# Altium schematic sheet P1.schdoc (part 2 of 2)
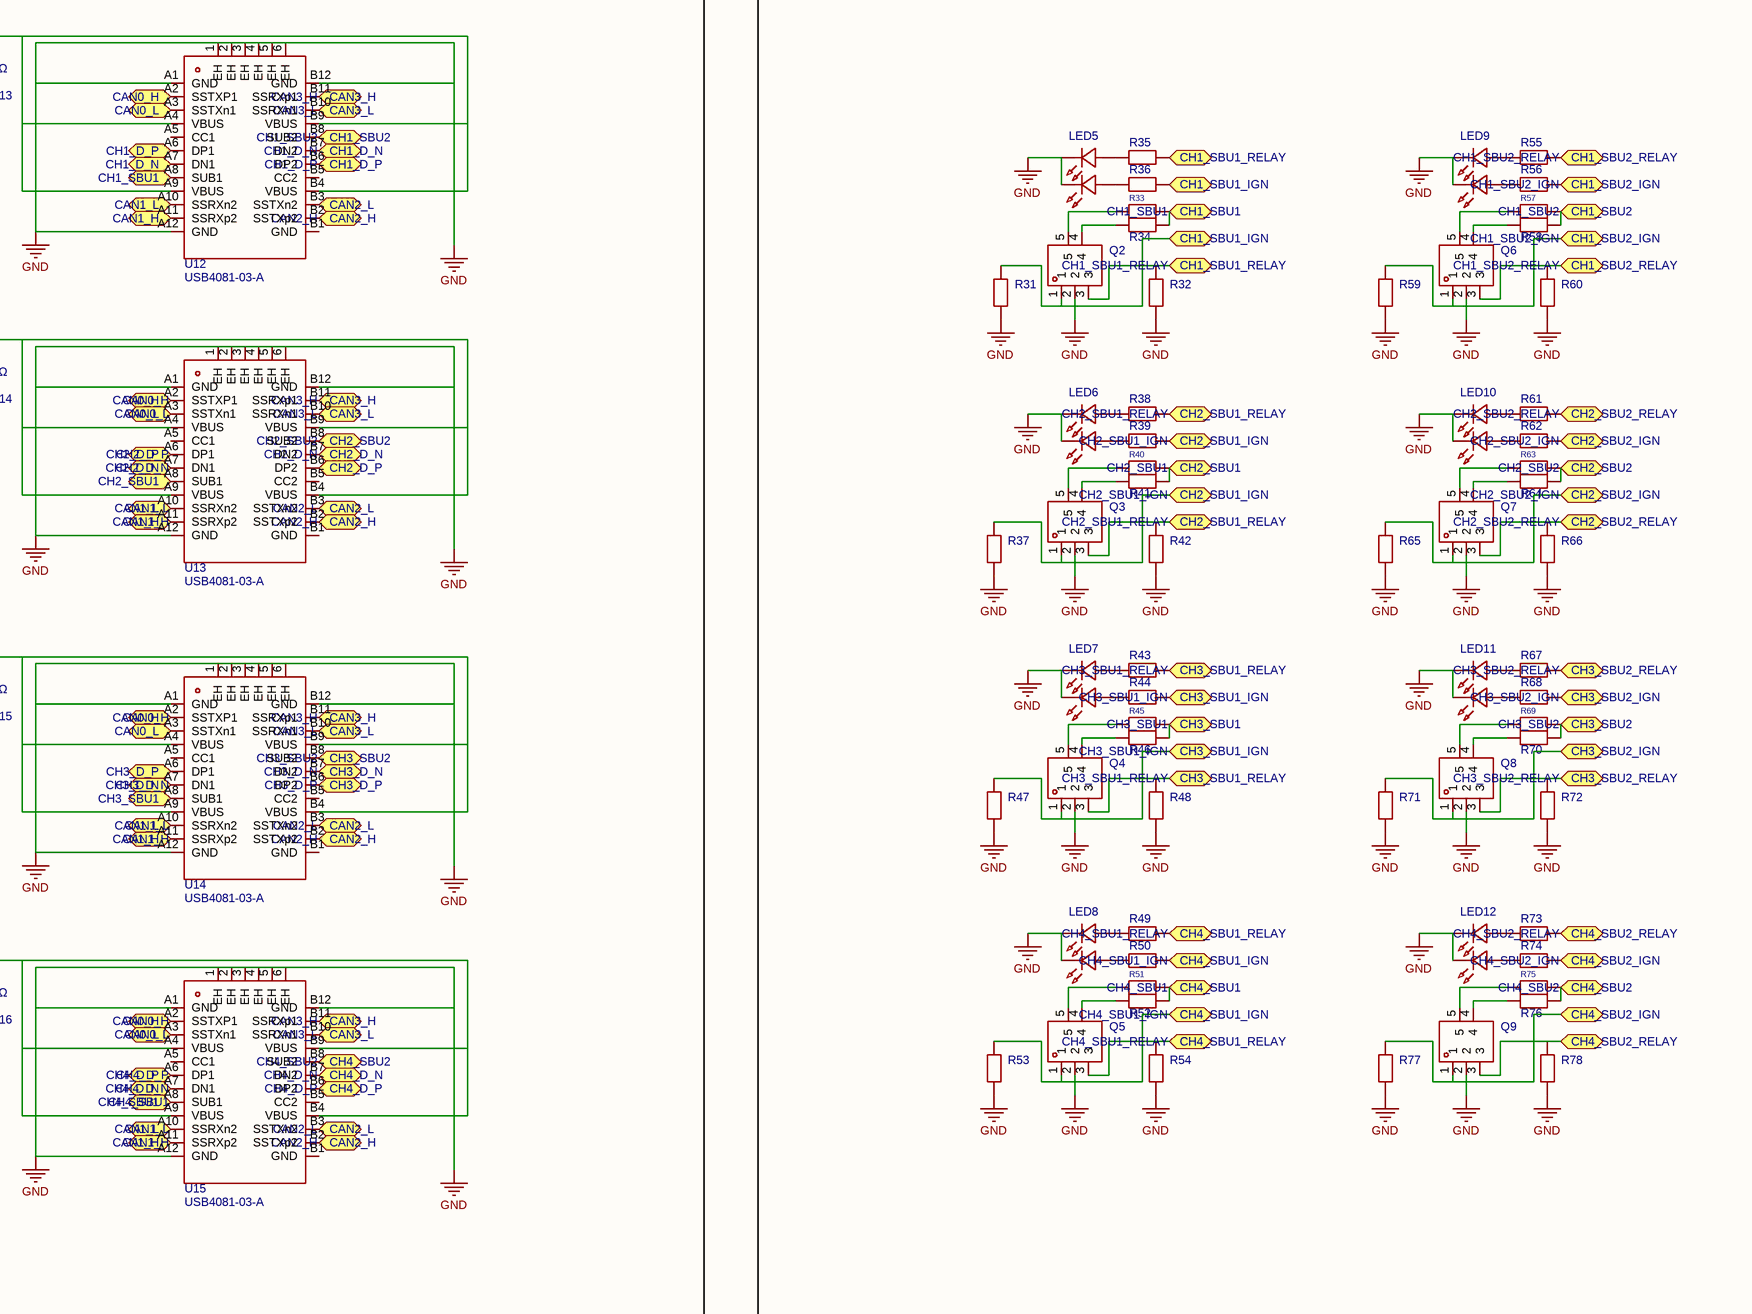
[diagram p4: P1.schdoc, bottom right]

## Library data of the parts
C1 C2 C7 C8 C13 C30 C31 C37 = CL05A106MQ5NUNC: Capacitance:10uF Tolerance:±20% Tolerance:±20% Voltage Rating:6.3V Temperature Coefficient:X5R; Manufacturer: SAMSUNG(三星); AddInBom: yes; ModelId: b7d13df3e9464d7a99d0651d1a5b4d570819f05c4eef4c71ace90d822a990e87; ModelName: C0402_L1.0-W0.5-H0.5; ModelTransform: 39.37,19.685,0,0,0,0,0,0,0; Tolerance: ±20%; Voltage Rating: 6.3V; Temperature Coefficient: X5R
C3 C5 C6 C9 C11 C12 C14 C32-C36 = FCC0201X104K100ZT: Capacitance:100nF Tolerance:±10% Tolerance:±10% Voltage Rating:10V Temperature Coefficient:X5R Operating Temperature:-55℃~+85℃ Operating Temperature:-55℃~+85℃; Manufacturer: FOJAN(富捷); AddInBom: yes; ModelId: c3e75c3d90204c70b153866ab54c789f0819f05c4eef4c71ace90d822a990e87; ModelName: C0201_L0.6-W0.3-H0.3; ModelTransform: 23.622,11.811,0,0,0,0,0,0,0; Tolerance: ±10%; Voltage Rating: 10V; Temperature Coefficient: X5R
C4 C10 C15-C25 C40 C41 C46 C47 C50 C51 = FCC0201X104K100ZT: Capacitance:100nF Tolerance:±10% Tolerance:±10% Voltage Rating:10V Temperature Coefficient:X5R Operating Temperature:-55℃~+85℃ Operating Temperature:-55℃~+85℃; Manufacturer: FOJAN(富捷); 3D Model: c3e75c3d90204c70b153866ab54c789f0819f05c4eef4c71ace90d822a990e87; 3D Model Transform: 23.622,11.811,0,0,0,0,0,0,0; Tolerance: ±10%; Voltage Rating: 10V; Temperature Coefficient: X5R; AddInBom: yes; ModelName: C0201_L0.6-W0.3-H0.3
C26-C29 = GRM035R60G106ME01D: Capacitance:10uF Tolerance:±20% Tolerance:±20% Voltage Rating:4V Temperature Coefficient:X5R Operating Temperature:-55℃~+85℃ Operating Temperature:-55℃~+85℃; Manufacturer: muRata(村田); AddInBom: yes; ModelId: c3e75c3d90204c70b153866ab54c789f0819f05c4eef4c71ace90d822a990e87; ModelName: C0201_L0.6-W0.3-H0.3; ModelTransform: 23.622,11.811,0,0,0,0,0,0,0; Tolerance: ±20%; Voltage Rating: 4V; Temperature Coefficient: X5R
C38 = CGA1A2X7R1C221K030BA: Capacitance: Tolerance:±10% Tolerance:±10% Voltage Rated: Temperature Coefficient:; Manufacturer: TDK; AddInBom: yes; ModelId: c3e75c3d90204c70b153866ab54c789f0819f05c4eef4c71ace90d822a990e87; ModelName: C0201_L0.6-W0.3-H0.3; ModelTransform: 23.622,11.811,0,0,0,0,0,0,0; Tolerance: ±10%
C39 C48 C49 C52 = CL05A106MQ5NUNC: Capacitance:10uF Tolerance:±20% Tolerance:±20% Voltage Rating:6.3V Temperature Coefficient:X5R; Manufacturer: SAMSUNG(三星); 3D Model: b7d13df3e9464d7a99d0651d1a5b4d570819f05c4eef4c71ace90d822a990e87; 3D Model Transform: 39.37,19.685,0,0,0,0,0,0,0; Tolerance: ±20%; Voltage Rating: 6.3V; Temperature Coefficient: X5R; AddInBom: yes; ModelName: C0402_L1.0-W0.5-H0.5
C42 C43 C45 C53 = C0201C0G120G500NTA: Capacitance:12pF Tolerance:±2% Tolerance:±2% Voltage Rating:50V Temperature Coefficient:C0G; Manufacturer: EYANG(宇阳科技); AddInBom: yes; ModelId: c3e75c3d90204c70b153866ab54c789f0819f05c4eef4c71ace90d822a990e87; ModelName: C0201_L0.6-W0.3-H0.3; ModelTransform: 23.622,11.811,0,0,0,0,0,0,0; Tolerance: ±2%; Voltage Rating: 50V; Temperature Coefficient: C0G
C44 = GRM035R60G106ME01D: Capacitance:10uF Tolerance:±20% Tolerance:±20% Voltage Rating:4V Temperature Coefficient:X5R Operating Temperature:-55℃~+85℃ Operating Temperature:-55℃~+85℃; Manufacturer: muRata(村田); 3D Model: c3e75c3d90204c70b153866ab54c789f0819f05c4eef4c71ace90d822a990e87; 3D Model Transform: 23.622,11.811,0,0,0,0,0,0,0; Tolerance: ±20%; Voltage Rating: 4V; Temperature Coefficient: X5R; AddInBom: yes; ModelName: C0201_L0.6-W0.3-H0.3
CN1 = DIP2*4P双排弯脚排母间距2.0mm塑长6.35塑高4.0ROHS散装: AddInBom: yes; ModelId: c57451f817604e0fb7e1537079d771660819f05c4eef4c71ace90d822a990e87; ModelTransform: 334.68437,393.7,0,0,0,0,0,-148.622,-137.795
D1 = B140WS-7: Diode Configuration:1 Independent Voltage - Forward(Vf@If):620mV@1A Voltage - DC Reverse(Vr):40V Current - Rectified:1A Reverse Leakage Current (Ir):50uA@40V Operating Junction Temperature Range:-40℃~+125℃ Operating Junction Temperature Range:-40℃~+125℃ N; Manufacturer: DIODES(美台); AddInBom: yes; ModelId: 533ebfb2f206414f9035ed0ccba1097d0819f05c4eef4c71ace90d822a990e87; ModelTransform: 104.3305,51.181,0,0,0,0,0,-0.004,0; Voltage - DC Reverse(Vr): 40V; Current - Rectified: 1A; Non-Repetitive Peak Forward Surge Current: 3A
D2 = SOD-323: Symbol: SOD-323_C9900016728; AddInBom: yes; ModelId: cca08871ec5d4aa980e515ff41a27b850819f05c4eef4c71ace90d822a990e87; ModelTransform: 98.425,51.181,0,0,0,0,-0.001,0.006,0
J1 = DC-044D-2.5A-2.0-SMT: Connector Type:DC Power Jack Mounting Type:Panel Mount Inside Contact Diameter:2mm Outside Contact Diameter:6mm Current Rating:2.5A Voltage Rating (Max):24V Body Height:7mm Length:13.5mm Width:11.6mm Operating Temperature:-20℃~+70℃ Operating Temperature:-; Manufacturer: XKB Connection(中国星坤); AddInBom: yes; ModelId: d7bd212643194dba976253cfc9f8ab800819f05c4eef4c71ace90d822a990e87; ModelTransform: 535.432,460.629,0,0,0,0,0,104.333,-78.74; Inside Contact Diameter: 2mm; Outside Contact Diameter: 6mm; Current Rating: 2.5A; Voltage Rating (Max): 24V; Body Height: 7mm
J2 = SSQ-104-04-T-D: Pitch:2.54mm Row Spacing:2.54mm Mounting Type:Through Hole Number of Rows:2 Number of Positions:8P Voltage Rating (Max):- Insulation Height:8.51mm Contact Plating:Tin Operating Temperature:-55℃~+105℃ Operating Temperature:-55℃~+105℃; Manufacturer: SAMTEC; AddInBom: yes; Pitch: 2.54mm; Number of Positions: 8P
L1 L2 = MLF1608A3R3KTA00: Inductance:3.3uH Tolerance:±10% Tolerance:±10% Current Rating:30mA Current - Saturation (Isat):- DC Resistance(DCR):550mΩ Q @ Frequency:35@10MHz Frequency - Self Resonant:65MHz Ratings:-; Manufacturer: TDK; AddInBom: yes; ModelId: ece81e7160a84e0c9a4133ba5d41d18a0819f05c4eef4c71ace90d822a990e87; ModelName: L0603_L1.6-W0.8-H0.5_BEAD; ModelTransform: 62.992,31.496,0,180,0,0,0.094,0.629,0; Tolerance: ±10%; Current Rating: 30mA; DC Resistance(DCR): 550mΩ; Frequency - Self Resonant: 65MHz
L3-L6 = ACM2012-900-2P-T001: Number of Lines:2 Inductance @ Frequency:- Current Rating:400mA Impedance @ Frequency:90Ω@100MHz Voltage Rating - DC:50V Voltage Withstand:- DC Resistance(DCR):190mΩ Operating Temperature:-40℃~+105℃ Operating Temperature:-40℃~+105℃ Insulation Resistance(I; Manufacturer: TDK; AddInBom: yes; ModelId: 1fa5967a6f9347dba85b8b48af48c5040819f05c4eef4c71ace90d822a990e87; ModelName: SMD-4_L2.0-W1.2-H1.3; ModelTransform: 79.527,47.244,0,0,0,0,0,0,0; Number of Lines: 2; Current Rating: 400mA; Voltage Rating - DC: 50V; DC Resistance(DCR): 190mΩ; Insulation Resistance(IR): 10MΩ
L7 = MLF1005G2R2JT: Inductance: Tolerance:±5% Tolerance:±5% Rated Current: Saturation Current (Isat):- DC Resistance (DCR): Q @ Freq:30@10MHz Frequency - Self Resonant:80MHz Ratings:; Manufacturer: TDK; AddInBom: yes; ModelId: aef00b1603224fd68a96e37121ccc9160819f05c4eef4c71ace90d822a990e87; ModelName: L0402_L1.0-W0.5-H0.5_BEAD; ModelTransform: 39.37,19.685,0,0,0,0,0,0.0005,0; Tolerance: ±5%; Frequency - Self Resonant: 80MHz
L8 = MLF1608A3R3KTA00: Inductance:3.3uH Tolerance:±10% Tolerance:±10% Current Rating:30mA Current - Saturation (Isat):- DC Resistance(DCR):550mΩ Q @ Frequency:35@10MHz Frequency - Self Resonant:65MHz Ratings:-; Manufacturer: TDK; 3D Model: ece81e7160a84e0c9a4133ba5d41d18a0819f05c4eef4c71ace90d822a990e87; 3D Model Transform: 62.992,31.496,0,180,0,0,0.094,0.629,0; Tolerance: ±10%; Current Rating: 30mA; DC Resistance(DCR): 550mΩ; Frequency - Self Resonant: 65MHz; AddInBom: yes; ModelName: L0603_L1.6-W0.8-H0.5_BEAD
LED1-LED4 = APHHS1005LSECK/J3-PF: Lamp Holder Type:- Illumination Color:Red Voltage - Forward(Vf):1.8V Voltage - Forward(Vf):1.8V Power(Watts):84mW Forward Current:2mA Wavelength - Dominant:625nm Wavelength - Dominant:625nm Peak Wavelength:640nm Diode Configuration:Discrete Diode Lens Col; Manufacturer: Kingbright(今台); AddInBom: yes; ModelId: 40582407f83840798c653124388df4d10819f05c4eef4c71ace90d822a990e87; ModelTransform: 40.1574,19.685,0,0,0,0,0,0,0; Illumination Color: Red; Voltage - Forward(Vf): 1.8V; Power(Watts): 84mW; Forward Current: 2mA; Wavelength - Dominant: 625nm; Peak Wavelength: 640nm; Lens Color: Water Clear; Luminous Intensity: 80mcd; Viewing Angle: 120°
LED5-LED12 = HSMF-C163: Lamp Holder Type:1.6mm x 0.8mm square LED Illumination Color:Red, Emerald Green Voltage - Forward(Vf):1.9V；3.4V Voltage - Forward(Vf):1.9V；3.4V Power(Watts):48mW；38mW Test Current:10mA；20mA Wavelength - Dominant:626nm；525nm Wavelength - Dominant:626nm；525; Manufacturer: Broadcom(博通); AddInBom: yes; ModelId: d063fd337c064f11a565633fccea839d0819f05c4eef4c71ace90d822a990e87; ModelTransform: 62.992,31.53537,0,0,0,0,0,0,0; Peak Wavelength: 637nm；523nm; Lens Color: White Lens; Luminous Intensity: 90mcd；45mcd; Viewing Angle: 120°
LED13-LED16 = SLED-0603-H0_8MM_C9900013124: AddInBom: yes; ModelId: 5eb0caa4a4a8448d821f86e8aa7b6b2f0819f05c4eef4c71ace90d822a990e87; ModelName: LED0603-RD_RED; ModelTransform: 63.7794,31.496,0,0,0,0,0,0,0
LED17 = TZ1615RGB3U-Common Yang: Illumination Color:Red, Emerald Green, Blue Voltage - Forward(Vf):2.6V~3V；1.8V~2.1V；2.4V~2.8V Voltage - Forward(Vf):2.6V~3V；1.8V~2.1V；2.4V~2.8V Power(Watts):60mW；90mW；90mW Forward Current:30mA Wavelength - Dominant:520nm~523nm；466nm~469nm；620nm~625nm Wave; Manufacturer: TUOZHAN(拓展光电); AddInBom: yes; ModelId: 05de422830ad44b2b67c76f4c68136bf0819f05c4eef4c71ace90d822a990e87; ModelTransform: 63.07074,59.055,0,0,0,0,0,0,0; Forward Current: 30mA; Luminous Intensity: 1000mcd；300mcd；200mcd; Viewing Angle: 120°
Q1 = AON2403: Number:1 P-Channel Drain to Source Voltage:12V Current - Continuous Drain(Id):8A RDS(on):21mΩ@4.5V Pd - Power Dissipation:2.8W Gate Threshold Voltage (Vgs(th)):900mV Gate Charge(Qg):18nC@4.5V Input Capacitance(Ciss):1.37nF Reverse Transfer Capacitance (Cr; Manufacturer: AOS; AddInBom: yes; ModelId: 2b7ac82e4c6346c0a85e441d81feff890819f05c4eef4c71ace90d822a990e87; ModelTransform: 78.74,78.819,0,0,0,0,-0.787,0,0; Drain to Source Voltage: 12V; Current - Continuous Drain(Id): 8A; Pd - Power Dissipation: 2.8W; Gate Threshold Voltage (Vgs(th)): 900mV; Input Capacitance(Ciss): 1.37nF; Reverse Transfer Capacitance (Crss@Vds): 258pF; Output Capacitance(Coss): 350pF; Vgs: ±8V
Q2-Q9 = QS5K2TR: Number:2 N-Channel Drain to Source Voltage:30V Current - Continuous Drain(Id):2A RDS(on):154mΩ@2.5V Pd - Power Dissipation:1.25W Gate Threshold Voltage (Vgs(th)):1.5V Gate Charge(Qg):3.9nC@15V Input Capacitance(Ciss):175pF Reverse Transfer Capacitance (Cr; Manufacturer: ROHM(罗姆); AddInBom: yes; ModelId: 27d509c6f913468487f8e947e5bcf8d80819f05c4eef4c71ace90d822a990e87; ModelTransform: 114.173,110.236,0,270,0,0,0,0,0; Drain to Source Voltage: 30V; Current - Continuous Drain(Id): 2A; Pd - Power Dissipation: 1.25W; Gate Threshold Voltage (Vgs(th)): 1.5V; Input Capacitance(Ciss): 175pF; Reverse Transfer Capacitance (Crss@Vds): 25pF; Configuration: Common source; Output Capacitance(Coss): 50pF; Vgs: ±12V
R1 = WR02X5232FAL: Type:Thick Film Resistors Resistance: Tolerance:±1% Tolerance:±1% Power(Watts): Overload Voltage (Max): Temperature Coefficient:±200ppm/℃ Temperature Coefficient:±200ppm/℃ Operating Temperature Range:-55℃~+125℃ Operating Temperature Range:-55℃~+125℃; Manufacturer: Walsin(华新科); AddInBom: yes; ModelId: d3c6830bf3df48b598874c11a7d9c8170819f05c4eef4c71ace90d822a990e87; ModelName: R0201_L0.6-W0.3-H0.3; ModelTransform: 23.622,11.811,0,0,0,0,0,-0.0005,0; Tolerance: ±1%
R2-R4 R9 R10 R15 R16 R19 R20 R23 R24 R27 R28 R31 R32 R37 R42 R47 R48 R53 R54 R59 R60 R65 R66 R71 R72 R77 R78 = SY0201DE10KP: Type:Thick Film Resistors Resistance: Tolerance:±0.5% Tolerance:±0.5% Power(Watts):- Overload Voltage (Max):- Temperature Coefficient:±50ppm/℃ Temperature Coefficient:±50ppm/℃ Operating Temperature Range:-55℃~+125℃ Operating Temperature Range:-55℃~+125℃; Manufacturer: SANYEAR(叁叶源); AddInBom: yes; ModelId: d3c6830bf3df48b598874c11a7d9c8170819f05c4eef4c71ace90d822a990e87; ModelName: R0201_L0.6-W0.3-H0.3; ModelTransform: 23.622,11.811,0,0,0,0,0,-0.0005,0; Tolerance: ±0.5%
R5 R33 R40 R45 R51 R57 R63 R69 R75 = RC0201BR-071KL: Type:Thick Film Resistor Resistance:1kΩ Tolerance:±0.1% Tolerance:±0.1% Power(Watts):50mW Temperature Coefficient:±200ppm/℃ Temperature Coefficient:±200ppm/℃ Operating Temperature:-55℃~+125℃ Operating Temperature:-55℃~+125℃; Manufacturer: YAGEO(国巨); AddInBom: yes; ModelId: d3c6830bf3df48b598874c11a7d9c8170819f05c4eef4c71ace90d822a990e87; ModelName: R0201_L0.6-W0.3-H0.3; ModelTransform: 23.622,11.811,0,0,0,0,0,-0.0005,0; Tolerance: ±0.1%; Power(Watts): 50mW
R6-R8 R17 R21 R25 R29 = SY0201DD100KP: Type:Thick Film Resistors Resistance:100kΩ Tolerance:±0.5% Tolerance:±0.5% Power(Watts):- Voltage-Supply(Max):- Temperature Coefficient:±25ppm/℃ Temperature Coefficient:±25ppm/℃ Operating Temperature:-55℃~+125℃ Operating Temperature:-55℃~+125℃; Manufacturer: SANYEAR(叁叶源); AddInBom: yes; ModelId: d3c6830bf3df48b598874c11a7d9c8170819f05c4eef4c71ace90d822a990e87; ModelName: R0201_L0.6-W0.3-H0.3; ModelTransform: 23.622,11.811,0,0,0,0,0,-0.0005,0; Tolerance: ±0.5%
R11-R14 = RTT0162R0FTH: Type:Thick Film Resistor Resistance:62Ω Tolerance:±1% Tolerance:±1% Power(Watts):50mW Voltage-Supply(Max):25V Temperature Coefficient:±200ppm/℃ Temperature Coefficient:±200ppm/℃ Operating Temperature:-55℃~+125℃ Operating Temperature:-55℃~+125℃; Manufacturer: RALEC(旺诠); AddInBom: yes; ModelId: d3c6830bf3df48b598874c11a7d9c8170819f05c4eef4c71ace90d822a990e87; ModelName: R0201_L0.6-W0.3-H0.3; ModelTransform: 23.622,11.811,0,0,0,0,0,-0.0005,0; Tolerance: ±1%; Power(Watts): 50mW; Voltage-Supply(Max): 25V
R18 R22 R26 R30 = RM02FTN2701: Resistance:2.7kΩ Tolerance:±1% Tolerance:±1% Power(Watts):50mW Temperature Coefficient:±200ppm/℃ Temperature Coefficient:±200ppm/℃; Manufacturer: 大毅科技; AddInBom: yes; ModelId: d3c6830bf3df48b598874c11a7d9c8170819f05c4eef4c71ace90d822a990e87; ModelName: R0201_L0.6-W0.3-H0.3; ModelTransform: 23.622,11.811,0,0,0,0,0,-0.0005,0; Tolerance: ±1%; Power(Watts): 50mW
R34-R36 R38 R39 R41 R43 R44 R46 R49 R50 R52 R55 R56 R58 R61 R62 R64 R67 R68 R70 R73 R74 R76 = CR0201J100RQ15Z: Type:Thick Film Resistor Resistance:100Ω Tolerance:±5% Tolerance:±5% Power(Watts):50mW Voltage-Supply(Max):25V Temperature Coefficient:±200ppm/℃ Temperature Coefficient:±200ppm/℃ Operating Temperature:-55℃~+155℃ Operating Temperature:-55℃~+155℃; Manufacturer: EVER OHMS(天二科技); AddInBom: yes; ModelId: d3c6830bf3df48b598874c11a7d9c8170819f05c4eef4c71ace90d822a990e87; ModelName: R0201_L0.6-W0.3-H0.3; ModelTransform: 23.622,11.811,0,0,0,0,0,-0.0005,0; Tolerance: ±5%; Power(Watts): 50mW; Voltage-Supply(Max): 25V
R79 R83 R86 R89 = RC-01W2802FT: Type:Thick Film Resistor Resistance:28kΩ Tolerance:±1% Tolerance:±1% Power(Watts):50mW Voltage-Supply(Max):25V Temperature Coefficient:±200ppm/℃ Temperature Coefficient:±200ppm/℃ Operating Temperature:-55℃~+125℃ Operating Temperature:-55℃~+125℃; Manufacturer: FH(风华); AddInBom: yes; ModelId: d3c6830bf3df48b598874c11a7d9c8170819f05c4eef4c71ace90d822a990e87; ModelName: R0201_L0.6-W0.3-H0.3; ModelTransform: 23.622,11.811,0,0,0,0,0,-0.0005,0; Tolerance: ±1%; Power(Watts): 50mW; Voltage-Supply(Max): 25V
R80 R82 R85 R88 = AC0201FR-0733KL: Type:Thick Film Resistors Resistance: Tolerance:±1% Tolerance:±1% Power(Watts): Overload Voltage (Max): Temperature Coefficient:±200ppm/℃ Temperature Coefficient:±200ppm/℃ Operating Temperature Range:-55℃~+155℃ Operating Temperature Range:-55℃~+155℃; Manufacturer: YAGEO(国巨); AddInBom: yes; ModelId: d3c6830bf3df48b598874c11a7d9c8170819f05c4eef4c71ace90d822a990e87; ModelName: R0201_L0.6-W0.3-H0.3; ModelTransform: 23.622,11.811,0,0,0,0,0,-0.0005,0; Tolerance: ±1%
R81 R84 R87 R90 = 0201WMJ0332TCE: Type:Thick Film Resistors Resistance:3.3kΩ Tolerance:±5% Tolerance:±5% Power(Watts): Overload Voltage (Max): Temperature Coefficient:±200ppm/℃ Temperature Coefficient:±200ppm/℃ Operating Temperature Range:-55℃~+155℃ Operating Temperature Range:-55℃~+155℃; Manufacturer: UNI-ROYAL(厚声); AddInBom: yes; ModelId: d3c6830bf3df48b598874c11a7d9c8170819f05c4eef4c71ace90d822a990e87; ModelName: R0201_L0.6-W0.3-H0.3; ModelTransform: 23.622,11.811,0,0,0,0,0,-0.0005,0; Tolerance: ±5%
R91-R93 = RC0201BR-071KL: Type:Thick Film Resistor Resistance:1kΩ Tolerance:±0.1% Tolerance:±0.1% Power(Watts):50mW Temperature Coefficient:±200ppm/℃ Temperature Coefficient:±200ppm/℃ Operating Temperature:-55℃~+125℃ Operating Temperature:-55℃~+125℃; Manufacturer: YAGEO(国巨); 3D Model: d3c6830bf3df48b598874c11a7d9c8170819f05c4eef4c71ace90d822a990e87; 3D Model Transform: 23.622,11.811,0,0,0,0,0,-0.0005,0; Tolerance: ±0.1%; Power(Watts): 50mW; AddInBom: yes; ModelName: R0201_L0.6-W0.3-H0.3
R94-R101 R122 R123 = SY0201DD100KP: Type:Thick Film Resistors Resistance:100kΩ Tolerance:±0.5% Tolerance:±0.5% Power(Watts):- Voltage-Supply(Max):- Temperature Coefficient:±25ppm/℃ Temperature Coefficient:±25ppm/℃ Operating Temperature:-55℃~+125℃ Operating Temperature:-55℃~+125℃; Manufacturer: SANYEAR(叁叶源); 3D Model: d3c6830bf3df48b598874c11a7d9c8170819f05c4eef4c71ace90d822a990e87; 3D Model Transform: 23.622,11.811,0,0,0,0,0,-0.0005,0; Tolerance: ±0.5%; AddInBom: yes; ModelName: R0201_L0.6-W0.3-H0.3
R102-R108 R115 R116 R119-R121 = SY0201DE10KP: Type:Thick Film Resistors Resistance: Tolerance:±0.5% Tolerance:±0.5% Power(Watts):- Overload Voltage (Max):- Temperature Coefficient:±50ppm/℃ Temperature Coefficient:±50ppm/℃ Operating Temperature Range:-55℃~+125℃ Operating Temperature Range:-55℃~+125℃; Manufacturer: SANYEAR(叁叶源); 3D Model: d3c6830bf3df48b598874c11a7d9c8170819f05c4eef4c71ace90d822a990e87; 3D Model Transform: 23.622,11.811,0,0,0,0,0,-0.0005,0; Tolerance: ±0.5%; AddInBom: yes; ModelName: R0201_L0.6-W0.3-H0.3
R109-R114 = CR0201J0R00Q15Z: Type:Thick Film Resistors Resistance: Tolerance:±5% Tolerance:±5% Power(Watts):- Operating Temperature Range:-55℃~+155℃ Operating Temperature Range:-55℃~+155℃; Manufacturer: EVER OHMS(天二科技); AddInBom: yes; ModelId: d3c6830bf3df48b598874c11a7d9c8170819f05c4eef4c71ace90d822a990e87; ModelName: R0201_L0.6-W0.3-H0.3; ModelTransform: 23.622,11.811,0,0,0,0,0,-0.0005,0; Tolerance: ±5%
R117 = TNPW020112K0BEED: Type:Thin Film Resistor Resistance:12kΩ Tolerance:±0.1% Tolerance:±0.1% Power(Watts):75mW Voltage-Supply(Max):25V Temperature Coefficient:±25ppm/℃ Temperature Coefficient:±25ppm/℃ Operating Temperature:-55℃~+155℃ Operating Temperature:-55℃~+155℃; Manufacturer: VISHAY(威世); AddInBom: yes; ModelId: d3c6830bf3df48b598874c11a7d9c8170819f05c4eef4c71ace90d822a990e87; ModelName: R0201_L0.6-W0.3-H0.3; ModelTransform: 23.622,11.811,0,0,0,0,0,-0.0005,0; Tolerance: ±0.1%; Power(Watts): 75mW; Voltage-Supply(Max): 25V
R118 = 0402WGF1004TCE: Type:Thick Film Resistor Resistance:1MΩ Tolerance:±1% Tolerance:±1% Power(Watts):62.5mW Voltage-Supply(Max):50V Temperature Coefficient:±100ppm/℃ Temperature Coefficient:±100ppm/℃ Operating Temperature:-55℃~+155℃ Operating Temperature:-55℃~+155℃; Manufacturer: UNI-ROYAL(厚声); AddInBom: yes; ModelId: efdecb7dae4442949d28eecaf748420f0819f05c4eef4c71ace90d822a990e87; ModelName: R0402_L1.0-W0.5-H0.4; ModelTransform: 39.37,19.685,0,0,0,0,0,0,0; Tolerance: ±1%; Power(Watts): 62.5mW; Voltage-Supply(Max): 50V
SCREW1-SCREW4 = Screw-Hole-M2: AddInBom: yes
SW1 = TS-1809-T20: AddInBom: yes; ModelId: bd147ff6519e42f69c39d1c99ae03a4c0819f05c4eef4c71ace90d822a990e87; ModelTransform: 139.7635,188.976,0,0,0,0,12.835,0,-19.685
U1 U2 = AP62300Z6-7: Function:Step-down type Voltage - Supply:4.2V~18V Voltage - Supply:4.2V~18V Output Voltage:800mV~7V Output Voltage:800mV~7V Output Current:3A Frequency - Switching:750kHz Frequency - Switching:750kHz Operating Temperature:-40℃~+125℃ Operating Temperature:; Manufacturer: DIODES(美台); AddInBom: yes; ModelId: 349fcb4042cf4b66b1919769fa663fb80819f05c4eef4c71ace90d822a990e87; ModelTransform: 62.992,62.992,0,0,0,0,0,0,0; Output Current: 3A; Frequency - Switching: 750kHz; Number of Outputs: 1; Topology: Buck; Quiescent Current: 155uA; Switch tube (built-in/external): Built-in; Output Type: Adjustable
U3-U6 = MCP2542FDT-E/MNY: Type:CAN FD Transceiver Data Rate:8Mbps Voltage - Supply:4.5V~5.5V Voltage - Supply:4.5V~5.5V Current - Supply:70mA Operating Temperature:-40℃~+125℃ Operating Temperature:-40℃~+125℃ Number of Channels:1 Quiescent Supply Current:16uA Features:Short-Circuit; Manufacturer: MICROCHIP(美国微芯); AddInBom: yes; ModelId: e03f6f588ddd4c4e82510053fd465c750819f05c4eef4c71ace90d822a990e87; ModelName: TDFN-8_L3.0-W2.0-H0.8-P0.50; ModelTransform: 118.8974,78.74,0,0,0,0,0.015,-0.005,0; Data Rate: 8Mbps; Current - Supply: 70mA; Number of Channels: 1; Quiescent Supply Current: 16uA
U7 = NCS20071XV53T2G: Number of Channels:1 Rail to Rail:Rail-to-rail output Gain Bandwidth Product:3MHz Vos - Input Offset Voltage:4.5mV Input Offset Voltage Drift(Vos TC):4uV/℃ Slew Rate:2.8V/us Ib - Input Bias Current:200pA Input Offset Current(Ios):2pA Input Voltage Noise D; Manufacturer: onsemi(安森美); Symbol: NCS20071XV53T2G_1; AddInBom: yes; ModelId: 6dbc2d01c80d4668ace67d178e86fe550819f05c4eef4c71ace90d822a990e87; ModelName: SOT-553-5P_L1.6-W1.2-H0.6-LS1.6-P0.50; ModelTransform: 62.992,62.992,0,90,0,0,1.331,-1.02,0; Number of Channels: 1; Gain Bandwidth Product: 3MHz; Vos - Input Offset Voltage: 4.5mV; Input Offset Voltage Drift(Vos TC): 4uV/℃; Ib - Input Bias Current: 200pA; Input Offset Current(Ios): 2pA; Input Voltage Noise Density: 30nV/√Hz@1kHz; Common Mode Rejection Ratio(CMRR): 135dB; Quiescent Current: 420uA; Output Current: 50mA; Single supply: 2.7V~36V; Dual Supply: -18V~-1.35V；1.35V~18V
U8-U10 = NCS20071XV53T2G: Number of Channels:1 Rail to Rail:Rail-to-rail output Gain Bandwidth Product:3MHz Vos - Input Offset Voltage:4.5mV Input Offset Voltage Drift(Vos TC):4uV/℃ Slew Rate:2.8V/us Ib - Input Bias Current:200pA Input Offset Current(Ios):2pA Input Voltage Noise D; Manufacturer: onsemi(安森美); Symbol: NCS20071XV53T2G_1; 3D Model: 6dbc2d01c80d4668ace67d178e86fe550819f05c4eef4c71ace90d822a990e87; 3D Model Transform: 62.992,62.992,0,90,0,0,1.331,-1.02,0; Number of Channels: 1; Gain Bandwidth Product: 3MHz; Vos - Input Offset Voltage: 4.5mV; Input Offset Voltage Drift(Vos TC): 4uV/℃; Ib - Input Bias Current: 200pA; Input Offset Current(Ios): 2pA; Input Voltage Noise Density: 30nV/√Hz@1kHz; Common Mode Rejection Ratio(CMRR): 135dB; Quiescent Current: 420uA; Output Current: 50mA; Single supply: 2.7V~36V; Dual Supply: -18V~-1.35V；1.35V~18V; AddInBom: yes; ModelName: SOT-553-5P_L1.6-W1.2-H0.6-LS1.6-P0.50
U11 U16-U18 = TPS25944ARVCR: Output Type:Open-drain Voltage - Supply:2.7V~18V Voltage - Supply:2.7V~18V Reset Active Level:Active Low Number of Voltages Monitored:1 Reset Timeout:220us Operating Temperature:-40℃~+85℃ Operating Temperature:-40℃~+85℃ Function:Watchdog timer Quiescent C; Manufacturer: TI(德州仪器); AddInBom: yes; ModelId: c34d53f6ed0544b58ed7f2e43a97796b0819f05c4eef4c71ace90d822a990e87; ModelName: WQFN-20_L4.0-W3.0-H0.8-P0.50; ModelTransform: 158.267,118.8974,0,0,0,0,-0.005,-0.003,0; Number of Voltages Monitored: 1; Reset Timeout: 220us; Quiescent Current: 200uA
U12 = USB4081-03-A: Symbol: USB4081-03-A_1; AddInBom: yes; ModelId: c4983a4d214d4f81818b58ef5c30d98b0819f05c4eef4c71ace90d822a990e87; ModelTransform: 351.988,307.285,0,0,0,0,0,-57.088,-62.992
U13-U15 U23 = USB4081-03-A: Symbol: USB4081-03-A_1; 3D Model: c4983a4d214d4f81818b58ef5c30d98b0819f05c4eef4c71ace90d822a990e87; 3D Model Transform: 351.988,307.285,0,0,0,0,0,-57.088,-62.992; AddInBom: yes
U19 = USB2517-JZX-TR: type:Hub USB Protocol:USB 2.0 Data Rate:480Mbps Voltage - Supply:- Voltage - Supply:- Operating Temperature:- Operating Temperature:- Memory Interface:I2C Current - Supply:- Quiescent Supply Current:- Number of Channels:7 Features:Programmable signal driv; Manufacturer: MICROCHIP(美国微芯); AddInBom: yes; ModelId: 0c3212b5632a40da9cbc374441e106f60819f05c4eef4c71ace90d822a990e87; ModelTransform: 355.117,355.117,0,0,0,0,0,0,0; USB Protocol: USB 2.0; Memory Interface: I2C; Number of Channels: 7
U20 = 24MHz: AddInBom: yes; ModelId: a2b47bc5d32f4dfd996128e047b549a00819f05c4eef4c71ace90d822a990e87; ModelTransform: 125.984,98.425,0,0,0,0,0,0,0
U21 = STM32H725ZGT6: CPU Core:ARM Cortex-M7 CPU Maximum Speed:550MHz Core Size:32 Bit Program Storage Size:1MB Program Memory Type:FLASH RAM Size:564KB EEPROM:- Number of I/O:97 Oscillator Type:Built-in Voltage - Supply:1.62V~3.6V Voltage - Supply:1.62V~3.6V Operating Tempera; Manufacturer: ST(意法半导体); AddInBom: yes; ModelId: f5adf0247e8d4ccabb0ebcd68b60a3700819f05c4eef4c71ace90d822a990e87; ModelTransform: 866.14,866.14,0,0,0,0,0,0,0; CPU Maximum Speed: 550MHz; Core Size: 32 Bit; Program Storage Size: 1MB; Program Memory Type: FLASH; RAM Size: 564KB; Number of I/O: 97
U22 = XDTP-1001-098: Card Connection Mode:Push-Push Card Type:MicroSD Card (TF Card) Connector Type:Connector and Ejector Additional Card Detection Pins:No Height Above Board:1.85mm Operating Temperature:-45℃~+80℃ Operating Temperature:-45℃~+80℃; Manufacturer: LX(连欣科技); Symbol: XDTP-1001-098_1; AddInBom: yes; Additional Card Detection Pins: No
X1 = NX2016SA-25MHZ-EXS00A-CS11365: Frequency:25MHz Normal temperature Frequency Tolerance:±30ppm Normal temperature Frequency Tolerance:±30ppm Load Capacitance: Frequency Stability:±40ppm Frequency Stability:±40ppm Equivalent Series Resistance(ESR):80Ω Operating Temperature: Operating Temp; Manufacturer: NDK; AddInBom: yes; ModelId: 7de1fd6717b24eac901503d31586dc410819f05c4eef4c71ace90d822a990e87; ModelTransform: 80.709,64.961,0,0,0,0,0,0,0; Normal temperature Frequency Tolerance: ±30ppm; Frequency Stability: ±40ppm; Equivalent Series Resistance(ESR): 80Ω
